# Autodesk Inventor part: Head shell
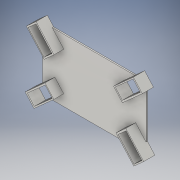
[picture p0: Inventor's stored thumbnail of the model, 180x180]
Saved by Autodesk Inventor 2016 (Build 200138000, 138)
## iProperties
Created: 2015-09
Part Number: Head shell
Material: Generic
Document SubType Name: Modeling
Designer: ChombaW
Density: 1 g/cm^3
Appearance: White
Author: ChombaW
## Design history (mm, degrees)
sketch "Sketch1"
  geometry: L1 (96.52, -58.42)-(-96.52, -58.42); L2 (-96.52, -58.42)-(-96.52, 58.42); L3 (-96.52, 58.42)-(96.52, 58.42); L4 (96.52, 58.42)-(96.52, -58.42); L5 (96.52, -58.42)-(-96.52, 58.42); L6 (-96.52, -58.42)-(96.52, 58.42); 1 further point
  constraints: 12 end point, 2 midpoint, 2 parallel, 1 horizontal, 1 perpendicular
  dimensions: "d0" = 193.04 distance of L2.end L3.end; "d1" = 116.84 distance of L1.end L2.end
extrude "Extrusion1" new body sketch "Sketch1" distance "d2" = 2.54; taper "d3" = 0 deg
sketch "Sketch2"
  geometry: L1 (-94.135, -70.973)-(-57.099, -37.742); L2 (-57.099, -37.742)-(-73.621, -19.329); L3 (-73.621, -19.329)-(-110.657, -52.559); L4 (-110.657, -52.559)-(-94.135, -70.973); L5 (-94.135, -70.973)-(-73.621, -19.329); L6 (-57.099, -37.742)-(-110.657, -52.559); L7 (58.776, -33.943)-(92.006, -70.979); L8 (92.006, -70.979)-(110.42, -54.457); L9 (110.42, -54.457)-(77.19, -17.421); L10 (77.19, -17.421)-(58.776, -33.943); L11 (58.776, -33.943)-(110.42, -54.457); L12 (92.006, -70.979)-(77.19, -17.421); L13 (70.834, 20.79)-(107.87, 54.021); L14 (107.87, 54.021)-(91.348, 72.435); L15 (91.348, 72.435)-(54.312, 39.204); L16 (54.312, 39.204)-(70.834, 20.79); L17 (70.834, 20.79)-(91.348, 72.435); L18 (107.87, 54.021)-(54.312, 39.204); L19 (70.834, 20.79)-(107.87, 54.021); L20 (107.87, 54.021)-(91.348, 72.435); L21 (91.348, 72.435)-(54.312, 39.204); L22 (54.312, 39.204)-(70.834, 20.79); L23 (70.834, 20.79)-(91.348, 72.435); L24 (107.87, 54.021)-(54.312, 39.204); L25 (-90.086, 71.458)-(-108.5, 54.936); L26 (-108.5, 54.936)-(-56.856, 34.422); L27 (-108.5, 54.936)-(-75.27, 17.9); L28 (-56.856, 34.422)-(-90.086, 71.458); L29 (-75.27, 17.9)-(-90.086, 71.458); L30 (-75.27, 17.9)-(-56.856, 34.422); L31 (96.52, -58.42)-(-96.52, -58.42) reference; L32 (96.52, 58.42)-(96.52, -58.42) reference; L33 (-96.52, 58.42)-(96.52, 58.42) reference; L34 (-96.52, -58.42)-(-96.52, 58.42) reference; 6 further points
  constraints: 60 end point, 10 midpoint, 10 parallel, 5 perpendicular
  dimensions: "d4" = 49.7586 distance of L3.end L2.end; "d5" = 24.7396 distance of L2.end L1.end; "d6" = 49.7586 distance of L9.end L8.end; "d7" = 24.7396 distance of L8.end L7.end; "d8" = 49.7586 distance of L15.end L14.end; "d9" = 24.7396 distance of L14.end L13.end; "d11" = 24.7396 distance of L20.end L19.end; "d12" = 49.7586 distance of L25.start L26.end; "d13" = 24.7396 distance of L26.end L27.end
extrude "Extrusion2" join sketch "Sketch2" distance "d14" = 18.288; taper "d15" = 0 deg; dims "d245" = 2.54, "d246" = 0
sketch "Sketch5"
  geometry: L1 (-93.473, -67.264)-(-60.047, -37.618); L2 (-60.047, -37.618)-(-73.328, -22.644); L3 (-73.328, -22.644)-(-106.754, -52.29); L4 (-106.754, -52.29)-(-93.473, -67.264); L5 (70.658, 24.626)-(104.084, 54.272); L6 (104.084, 54.272)-(90.803, 69.246); L7 (90.803, 69.246)-(57.377, 39.6); L8 (57.377, 39.6)-(70.658, 24.626); L9 (-105.222, 54.543)-(-75.576, 21.117); L10 (-75.576, 21.117)-(-60.602, 34.398); L11 (-60.602, 34.398)-(-90.248, 67.824); L12 (-90.248, 67.824)-(-105.222, 54.543); L13 (62.709, -34.345)-(92.355, -67.771); L14 (92.355, -67.771)-(107.329, -54.49); L15 (107.329, -54.49)-(77.683, -21.064); L16 (77.683, -21.064)-(62.709, -34.345); L17 (91.348, 72.435)-(107.87, 54.021) reference; L18 (110.42, -54.457)-(92.006, -70.979) reference; 1 further point
  constraints: 32 end point, 8 parallel, 4 perpendicular
  dimensions: "d22" = 44.6786 distance of L3.end L2.end; "d23" = 20.0152 distance of L2.end L1.end; "d24" = 44.6786 distance of L7.end L6.end; "d25" = 20.0152 distance of L6.end L5.end; "d26" = 44.6786 distance of L11.end L10.end; "d27" = 20.0152 distance of L10.end L9.end; "d28" = 44.6786 distance of L15.end L14.end; "d29" = 20.0152 distance of L14.end L13.end
extrude "Extrusion5" cut sketch "Sketch5" distance "d30" = 21.336; taper "d31" = 0 deg
body "Solid1"
node "Projected Loop1"
